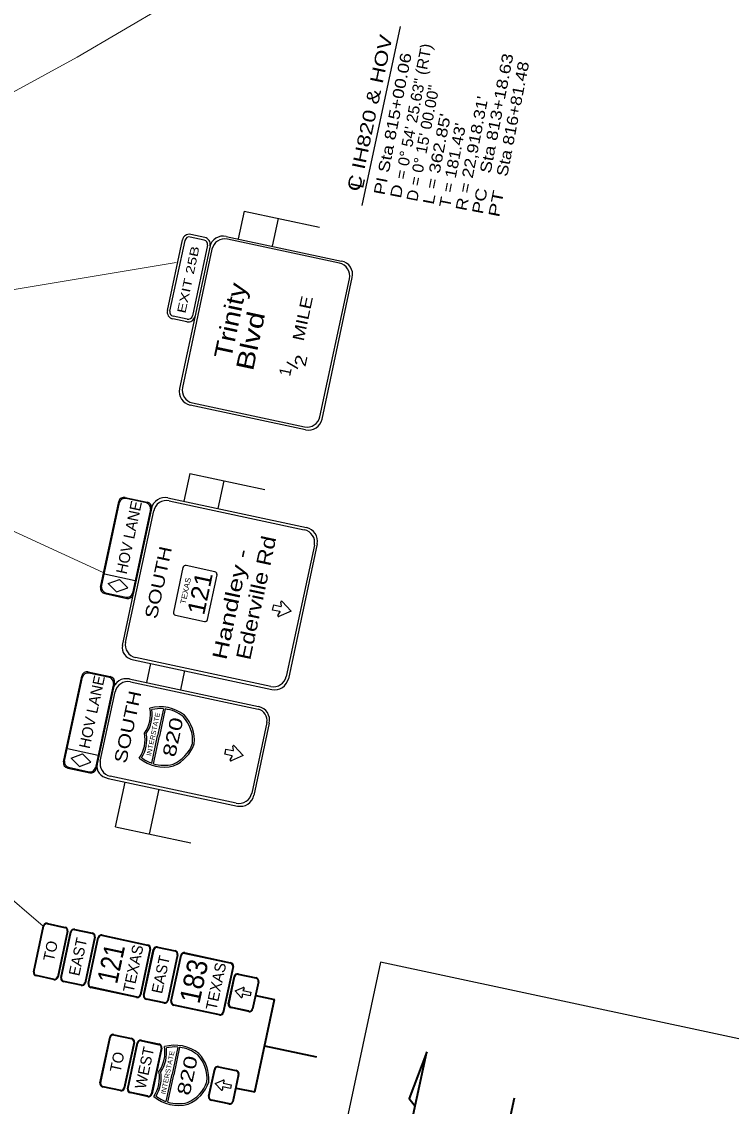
# Model space of a CAD drawing. Extents: x 2363411 to 2369702, y 6977197 to 6988655.
# Drawn here: x 2365781 to 2366546, y 6980518 to 6981687 of the extents above; entities that cross this region are included whole.
import ezdxf
from ezdxf.enums import TextEntityAlignment as Align

# ---------------------------------------------------------------- set-up
doc = ezdxf.new("R2010")
doc.units = 0
doc.header["$LTSCALE"] = 5.6
for name, color, linetype, lineweight in [('1', 7, 'Continuous', 25), ('48', 7, 'Continuous', 25), ('55', 7, 'Continuous', 35), ('61', 7, 'Continuous', 25)]:
    doc.layers.add(name, color=color, linetype=linetype, lineweight=lineweight)
doc.layers.add('28', color=7, linetype='Continuous')
doc.layers.add('33', color=7, linetype='Continuous')

msp = doc.modelspace()

# ---------------------------------------------------------------- linework, layer by layer
at = {"layer": '1'}
for p, q in [((2366020.874, 6981482.752), (2366014.484, 6981452.844)), ((2366020.874, 6981482.752), (2366101.929, 6981465.434)), ((2366057.546, 6981474.917), (2366051.157, 6981445.01)), ((2365937.928, 6981375.61), (2365954.223, 6981451.889)), ((2365940.673, 6981375.022), (2365956.98, 6981451.303)), ((2365977.633, 6981451.687), (2365962.542, 6981454.91)), ((2365978.222, 6981454.434), (2365963.131, 6981457.664)), ((2366001.485, 6981455.621), (2366125.875, 6981429.054)), ((2366123.454, 6981426.696), (2366002.732, 6981452.481)), ((2365983.992, 6981445.538), (2365951.081, 6981291.529)), ((2365986.041, 6981441.669), (2365954.233, 6981292.777)), ((2365981.232, 6981446.123), (2365964.937, 6981369.836)), ((2366102.449, 6981261.107), (2366134.266, 6981410)), ((2366104.809, 6981258.685), (2366137.408, 6981411.245)), ((2365959.371, 6981366.23), (2365944.283, 6981369.458)), ((2365958.785, 6981363.482), (2365943.692, 6981366.702)), ((2365965.044, 6981276.087), (2366085.763, 6981250.295)), ((2366087.009, 6981247.152), (2365962.62, 6981273.726)), ((2365962.059, 6981200.025), (2365955.669, 6981170.118)), ((2365962.059, 6981200.026), (2366043.114, 6981182.708)), ((2365998.731, 6981192.19), (2365992.342, 6981162.284)), ((2365938.629, 6981173.659), (2366088.081, 6981141.727)), ((2365939.875, 6981170.516), (2366085.66, 6981139.368)), ((2365889.641, 6981014.408), (2365920.825, 6981162.123)), ((2365892.852, 6981017.827), (2365923.184, 6981159.702)), ((2366099.617, 6981123.924), (2366068.501, 6980978.416)), ((2366096.474, 6981122.678), (2366066.211, 6980981.14)), ((2365989.318, 6981094.073), (2365958.086, 6981100.752)), ((2365954.749, 6981098.595), (2365944.455, 6981050.436)), ((2365981.189, 6981042.587), (2365991.483, 6981090.738)), ((2366052.66, 6981058.26), (2366060.262, 6981056.638)), ((2366060.882, 6981057.216), (2366060.308, 6981061.315)), ((2365946.622, 6981047.1), (2365977.854, 6981040.421)), ((2366057.212, 6981046.809), (2366059.404, 6981050.343)), ((2365901.323, 6980999.123), (2366050.766, 6980967.183)), ((2366049.52, 6980970.325), (2365903.73, 6981001.475)), ((2365919.718, 6980995.191), (2365915.286, 6980974.449)), ((2365956.392, 6980987.352), (2365951.96, 6980966.611)), ((2365896.913, 6980978.375), (2366036.356, 6980948.576)), ((2365898.167, 6980975.241), (2366035.77, 6980945.833)), ((2365862.329, 6980886.498), (2365879.794, 6980969.113)), ((2365865.54, 6980889.917), (2365881.463, 6980964.428)), ((2365933.712, 6980946.302), (2365927.444, 6980916.965)), ((2365935.604, 6980946.092), (2365929.295, 6980916.571)), ((2366045.2, 6980931.621), (2366028.906, 6980855.365)), ((2366047.89, 6980930.773), (2366031.196, 6980852.641)), ((2365921.179, 6980887.628), (2365927.444, 6980916.965)), ((2365922.988, 6980887.028), (2365929.295, 6980916.571)), ((2366001.085, 6980902.773), (2366008.687, 6980901.151)), ((2366009.307, 6980901.729), (2366008.733, 6980905.828)), ((2366005.637, 6980891.322), (2366007.829, 6980894.856)), ((2365874.011, 6980871.213), (2366013.471, 6980841.403)), ((2366012.224, 6980844.544), (2365876.418, 6980873.565)), ((2365882.061, 6980818.959), (2365892.386, 6980867.285)), ((2365918.732, 6980811.123), (2365929.06, 6980859.446)), ((2365882.061, 6980818.959), (2365963.115, 6980801.639)), ((2365949.29, 6980581.459), (2365943.024, 6980552.121)), ((2365951.181, 6980581.248), (2365944.872, 6980551.729)), ((2365936.757, 6980522.785), (2365943.024, 6980552.121)), ((2365938.564, 6980522.185), (2365944.872, 6980551.729))]:
    msp.add_line(p, q, dxfattribs=at)
at = {"layer": '1', "lineweight": 13}
for p, q in [((2365325.995, 6981323.206), (2365947.601, 6981427.566)), ((2365421.362, 6981299.52), (2365868.555, 6981093.178)), ((2365520.812, 6980952.701), (2365803.961, 6980712.038))]:
    msp.add_line(p, q, dxfattribs=at)
msp.add_lwpolyline([(2365607.98, 6981522.117), (2365840.659, 6981648.883), (2366127.574, 6981817.426)], dxfattribs=at)
at = {"layer": '1'}
for points in [[(2366059.08, 6981051.1), (2366051.464, 6981052.719), (2366052.058, 6981055.49), (2366052.66, 6981058.26)], [(2366061.633, 6981061.904), (2366071.396, 6981051.364), (2366058.176, 6981045.725)], [(2366007.505, 6980895.613), (2365999.889, 6980897.232), (2366000.483, 6980900.003), (2366001.085, 6980902.773)], [(2366010.058, 6980906.417), (2366019.821, 6980895.877), (2366006.601, 6980890.238)]]:
    msp.add_lwpolyline(points, dxfattribs=at)
for centre, radius, start, end in [((2365961.547, 6981450.334), 7.501, 77.93922, 167.93922), ((2365961.547, 6981450.334), 4.688, 77.93922, 167.93922), ((2365976.657, 6981447.105), 4.688, 347.93922, 77.93922), ((2365976.657, 6981447.105), 7.501, 347.93922, 77.93922), ((2365998.358, 6981440.961), 15.001, 77.93922, 167.93922), ((2365999.799, 6981438.736), 14.063, 77.93922, 167.93922), ((2366122.74, 6981414.385), 15.001, 347.93922, 77.93922), ((2366120.515, 6981412.943), 14.063, 347.93922, 77.93922), ((2365945.247, 6981374.049), 7.501, 167.93922, 257.93922), ((2365945.247, 6981374.049), 4.688, 167.93922, 257.93922), ((2365960.357, 6981370.82), 7.501, 257.93922, 347.93922), ((2365960.357, 6981370.82), 4.688, 257.93922, 347.93922), ((2365965.76, 6981288.398), 15.001, 167.93922, 257.93922), ((2365967.986, 6981289.84), 14.063, 167.93922, 257.93922), ((2366088.701, 6981264.047), 14.063, 257.93922, 347.93922), ((2366090.143, 6981261.822), 15.001, 257.93922, 347.93922), ((2365935.494, 6981158.989), 15.001, 77.94013, 167.94013), ((2365936.936, 6981156.763), 14.063, 77.94013, 167.94013), ((2366082.722, 6981125.616), 14.063, 347.94013, 77.94013), ((2366084.947, 6981127.058), 15.001, 347.94013, 77.94013), ((2365957.501, 6981098), 2.813, 77.93906, 167.93906), ((2365988.728, 6981091.328), 2.813, 347.93906, 77.93906), ((2366060.387, 6981057.133), 0.506, 257.93835, 7.92145), ((2366061.064, 6981061.413), 0.759, 42.67684, 188.05798), ((2365947.212, 6981049.847), 2.813, 167.93906, 257.93906), ((2365978.44, 6981043.175), 2.813, 257.93906, 347.93906), ((2366057.86, 6981046.415), 0.759, 147.81871, 293.19985), ((2366058.991, 6981050.598), 0.506, 327.95524, 77.93835), ((2365906.673, 6981015.225), 14.063, 167.94013, 257.94013), ((2365893.789, 6980963.712), 15.001, 77.94013, 167.94013), ((2365895.23, 6980961.486), 14.063, 77.94013, 167.94013), ((2366052.458, 6980984.078), 14.063, 257.94013, 347.94013), ((2366053.9, 6980981.852), 15.001, 257.94013, 347.94013), ((2365930.397, 6980906.367), 41.954, 51.80243, 105.50481), ((2366033.221, 6980933.907), 15, 347.93924, 77.93716), ((2365883.741, 6980940.564), 35.984, 325.11963, 9.96995), ((2365883.741, 6980940.564), 37.874, 326.31755, 7.31439), ((2365930.397, 6980906.367), 40.064, 85.24888, 103.11363), ((2365930.397, 6980906.367), 40.064, 52.01897, 82.53095), ((2365926.405, 6980911.766), 38.808, 355.77729, 42.42367), ((2365926.405, 6980911.766), 40.698, 355.41114, 42.64704), ((2366033.221, 6980933.907), 12.195, 347.93924, 77.93716), ((2365877.909, 6980913.269), 35.984, 325.90855, 10.75886), ((2365877.909, 6980913.269), 37.874, 328.56411, 9.56095), ((2365928.617, 6980922.117), 38.808, 293.45483, 340.10121), ((2365928.617, 6980922.117), 40.698, 293.23145, 340.46735), ((2366008.812, 6980901.647), 0.506, 257.93835, 7.92145), ((2366009.489, 6980905.927), 0.759, 42.67684, 188.05798), ((2365879.361, 6980887.315), 14.063, 167.94013, 257.94013), ((2365934.466, 6980925.413), 41.954, 230.37369, 284.07606), ((2365934.466, 6980925.413), 40.064, 232.76486, 250.62962), ((2366006.284, 6980890.929), 0.759, 147.81871, 293.19985), ((2366007.415, 6980895.111), 0.506, 327.95524, 77.93835), ((2365934.466, 6980925.413), 40.064, 253.34754, 283.85953), ((2366015.153, 6980858.303), 14.063, 257.94013, 347.94013), ((2366016.595, 6980856.077), 15.001, 257.94013, 347.94013), ((2365899.319, 6980575.722), 35.984, 325.11936, 9.96967), ((2365899.319, 6980575.722), 37.874, 326.31727, 7.31411), ((2365945.975, 6980541.524), 41.954, 51.80216, 105.50453), ((2365945.975, 6980541.524), 40.064, 85.2486, 103.11335), ((2365945.975, 6980541.524), 40.064, 52.01869, 82.53068), ((2365941.983, 6980546.923), 40.698, 355.41087, 42.64677), ((2365941.983, 6980546.923), 38.808, 355.77701, 42.42339), ((2365893.487, 6980548.426), 35.984, 325.90827, 10.75858), ((2365893.487, 6980548.426), 37.874, 328.56383, 9.56067), ((2365944.195, 6980557.274), 38.808, 293.45455, 340.10093), ((2365944.195, 6980557.274), 40.698, 293.23117, 340.46707), ((2365950.044, 6980560.57), 41.954, 230.37341, 284.07578), ((2365950.044, 6980560.57), 40.064, 232.76459, 250.62934), ((2365950.044, 6980560.57), 40.064, 253.34726, 283.85925)]:
    msp.add_arc(centre, radius, start, end, dxfattribs=at)
for centre in [(2365904.485, 6981011.715), (2365877.173, 6980883.805)]:
    msp.add_ellipse(centre, major_axis=(-15.18, 0), ratio=0.848877, start_param=6.07270093, end_param=7.64349725, dxfattribs=at)
at = {"layer": '48'}
for p, q in [((2365865.834, 6981077.419), (2365885.547, 6981169.662)), ((2365892.556, 6981174.204), (2365916.282, 6981169.134)), ((2365915.328, 6981168.208), (2365893.045, 6981172.969)), ((2365867.066, 6981077.911), (2365886.464, 6981168.708)), ((2365919.586, 6981161.629), (2365900.189, 6981070.832)), ((2365920.825, 6981162.123), (2365901.12, 6981069.878)), ((2365869.991, 6981091.6), (2365903.114, 6981084.522)), ((2365874.213, 6981081.201), (2365886.141, 6981085.701)), ((2365883.26, 6981072.218), (2365874.213, 6981081.201)), ((2365883.26, 6981072.218), (2365895.188, 6981076.719)), ((2365895.188, 6981076.719), (2365886.141, 6981085.701)), ((2365870.378, 6981070.406), (2365894.234, 6981065.309)), ((2365871.332, 6981071.335), (2365893.616, 6981066.572)), ((2365852.645, 6980986.009), (2365876.371, 6980980.939)), ((2365875.418, 6980980.013), (2365853.134, 6980984.774)), ((2365825.923, 6980889.224), (2365845.636, 6980981.467)), ((2365827.155, 6980889.716), (2365846.553, 6980980.513)), ((2365879.675, 6980973.434), (2365860.278, 6980882.637)), ((2365880.914, 6980973.928), (2365861.209, 6980881.683)), ((2365830.08, 6980903.405), (2365863.203, 6980896.327)), ((2365834.302, 6980893.006), (2365846.23, 6980897.506)), ((2365843.349, 6980884.023), (2365834.302, 6980893.006)), ((2365855.277, 6980888.524), (2365846.23, 6980897.506)), ((2365830.467, 6980882.211), (2365854.323, 6980877.114)), ((2365831.422, 6980883.14), (2365853.705, 6980878.377)), ((2365843.349, 6980884.023), (2365855.277, 6980888.524)), ((2365808.358, 6980714.239), (2365827.441, 6980710.162)), ((2365808.518, 6980714.991), (2365827.601, 6980710.913)), ((2365793.42, 6980662.707), (2365803.961, 6980712.038)), ((2365794.171, 6980662.547), (2365804.712, 6980711.877)), ((2365829.803, 6980706.516), (2365819.263, 6980657.185)), ((2365830.554, 6980706.356), (2365820.014, 6980657.025)), ((2365822.947, 6980656.398), (2365833.488, 6980705.729)), ((2365823.698, 6980656.238), (2365834.239, 6980705.568)), ((2365837.885, 6980707.93), (2365856.968, 6980703.853)), ((2365838.045, 6980708.682), (2365857.128, 6980704.604)), ((2365867.572, 6980702.373), (2365916.903, 6980691.832)), ((2365859.33, 6980700.207), (2365848.79, 6980650.876)), ((2365860.081, 6980700.047), (2365849.541, 6980650.716)), ((2365852.474, 6980650.089), (2365863.015, 6980699.42)), ((2365853.225, 6980649.929), (2365863.766, 6980699.259)), ((2365867.412, 6980701.622), (2365916.743, 6980691.081)), ((2365919.105, 6980687.435), (2365908.564, 6980638.104)), ((2365919.856, 6980687.275), (2365909.316, 6980637.944)), ((2365912.249, 6980637.317), (2365922.79, 6980686.648)), ((2365913, 6980637.157), (2365923.541, 6980686.487)), ((2365927.187, 6980688.849), (2365946.27, 6980684.772)), ((2365927.347, 6980689.601), (2365946.43, 6980685.523)), ((2365948.632, 6980681.126), (2365938.091, 6980631.795)), ((2365949.383, 6980680.966), (2365938.843, 6980631.635)), ((2365941.776, 6980631.008), (2365952.317, 6980680.339)), ((2365942.527, 6980630.848), (2365953.068, 6980680.178)), ((2365956.714, 6980682.541), (2366006.045, 6980672)), ((2365956.874, 6980683.292), (2366006.205, 6980672.751)), ((2366008.407, 6980668.354), (2365997.866, 6980619.023)), ((2366009.158, 6980668.194), (2365998.617, 6980618.863)), ((2365815.456, 6980654.072), (2365796.373, 6980658.149)), ((2365815.616, 6980654.823), (2365796.534, 6980658.9)), ((2366003.699, 6980628.288), (2366009.944, 6980657.514)), ((2366004.45, 6980628.128), (2366010.695, 6980657.354)), ((2366014.341, 6980659.716), (2366033.424, 6980655.639)), ((2366014.501, 6980660.467), (2366033.584, 6980656.39)), ((2365844.983, 6980647.763), (2365825.9, 6980651.84)), ((2365845.143, 6980648.514), (2365826.061, 6980652.591)), ((2365904.758, 6980634.991), (2365855.427, 6980645.531)), ((2365904.918, 6980635.742), (2365855.588, 6980646.282)), ((2366035.786, 6980651.993), (2366029.541, 6980622.767)), ((2366036.537, 6980651.832), (2366030.292, 6980622.606)), ((2365934.285, 6980628.682), (2365915.202, 6980632.759)), ((2365934.445, 6980629.433), (2365915.363, 6980633.51)), ((2365994.06, 6980615.91), (2365944.729, 6980626.45)), ((2365994.22, 6980616.661), (2365944.89, 6980627.201)), ((2366025.735, 6980619.653), (2366006.652, 6980623.731)), ((2366025.895, 6980620.404), (2366006.812, 6980624.482)), ((2365865.258, 6980542.937), (2365875.798, 6980592.268)), ((2365866.009, 6980542.777), (2365876.549, 6980592.107)), ((2365880.195, 6980594.469), (2365899.278, 6980590.392)), ((2365880.356, 6980595.221), (2365899.439, 6980591.143)), ((2365901.64, 6980586.746), (2365891.1, 6980537.415)), ((2365902.391, 6980586.586), (2365891.851, 6980537.255)), ((2365894.785, 6980536.628), (2365905.325, 6980585.959)), ((2365895.536, 6980536.468), (2365906.076, 6980585.798)), ((2365909.722, 6980588.16), (2365928.805, 6980584.083)), ((2365909.883, 6980588.912), (2365928.966, 6980584.834)), ((2365931.167, 6980580.437), (2365920.627, 6980531.106)), ((2365931.918, 6980580.277), (2365921.378, 6980530.946)), ((2365982.362, 6980528.427), (2365988.606, 6980557.653)), ((2365983.113, 6980528.266), (2365989.358, 6980557.492)), ((2365993.004, 6980559.855), (2366012.086, 6980555.777)), ((2365993.164, 6980560.606), (2366012.247, 6980556.528)), ((2366014.449, 6980552.131), (2366008.204, 6980522.905)), ((2366015.2, 6980551.971), (2366008.955, 6980522.745)), ((2365887.293, 6980534.302), (2365868.211, 6980538.379)), ((2365887.454, 6980535.053), (2365868.371, 6980539.13)), ((2365916.82, 6980527.993), (2365897.738, 6980532.07)), ((2365916.981, 6980528.744), (2365897.898, 6980532.821)), ((2366004.397, 6980519.792), (2365985.315, 6980523.869)), ((2366004.558, 6980520.543), (2365985.475, 6980524.62))]:
    msp.add_line(p, q, dxfattribs=at)
at = {"layer": '48', "lineweight": 40}
for p, q in [((2366032.186, 6980533.061), (2366053.523, 6980632.923)), ((2366033.415, 6980637.219), (2366053.523, 6980632.923)), ((2366042.854, 6980582.992), (2366098.689, 6980571.062)), ((2366012.077, 6980537.358), (2366032.186, 6980533.061))]:
    msp.add_line(p, q, dxfattribs=at)
at = {"layer": '48'}
for points in [[(2366017.428, 6980635.113), (2366010.943, 6980642.094), (2366019.637, 6980645.795)], [(2366020.627, 6980644.749), (2366019.484, 6980642.441), (2366028.139, 6980640.591), (2366027.295, 6980636.636), (2366018.639, 6980638.486), (2366018.772, 6980635.661)], [(2365996.09, 6980535.252), (2365989.606, 6980542.233), (2365998.299, 6980545.934)], [(2365999.29, 6980544.889), (2365998.147, 6980542.58), (2366006.801, 6980540.731), (2366005.957, 6980536.775), (2365997.302, 6980538.625), (2365997.434, 6980535.8)]]:
    msp.add_lwpolyline(points, dxfattribs=at)
for centre, radius, start, end in [((2365891.324, 6981168.427), 5.909, 77.93633, 167.93633), ((2365891.892, 6981167.55), 5.54, 77.93633, 167.93633), ((2365914.17, 6981162.786), 5.54, 347.93633, 77.93633), ((2365915.047, 6981163.354), 5.909, 347.93633, 77.93633), ((2365871.613, 6981076.184), 5.909, 167.93575, 257.93575), ((2365872.489, 6981076.752), 5.54, 167.93575, 257.93575), ((2365894.774, 6981071.99), 5.54, 257.93575, 347.93575), ((2365895.342, 6981071.113), 5.909, 257.93575, 347.93575), ((2365851.413, 6980980.232), 5.909, 77.93633, 167.93633), ((2365851.981, 6980979.355), 5.54, 77.93633, 167.93633), ((2365874.259, 6980974.591), 5.54, 347.93633, 77.93633), ((2365875.136, 6980975.159), 5.909, 347.93633, 77.93633), ((2365831.702, 6980887.989), 5.909, 167.93575, 257.93575), ((2365832.578, 6980888.557), 5.54, 167.93575, 257.93575), ((2365854.863, 6980883.794), 5.54, 257.93575, 347.93575), ((2365855.431, 6980882.918), 5.909, 257.93575, 347.93575), ((2365807.716, 6980711.235), 3.84, 77.93906, 167.93906), ((2365807.716, 6980711.235), 3.072, 77.93906, 167.93906), ((2365826.799, 6980707.158), 3.072, 347.93906, 77.93906), ((2365826.799, 6980707.158), 3.84, 347.93906, 77.93906), ((2365837.243, 6980704.926), 3.84, 77.93906, 167.93906), ((2365837.243, 6980704.926), 3.072, 77.93906, 167.93906), ((2365856.326, 6980700.849), 3.072, 347.93906, 77.93906), ((2365856.326, 6980700.849), 3.84, 347.93906, 77.93906), ((2365866.77, 6980698.617), 3.84, 77.93906, 167.93906), ((2365866.77, 6980698.617), 3.072, 77.93906, 167.93906), ((2365916.101, 6980688.077), 3.072, 347.93906, 77.93906), ((2365916.101, 6980688.077), 3.84, 347.93906, 77.93906), ((2365926.545, 6980685.845), 3.84, 77.93906, 167.93906), ((2365926.545, 6980685.845), 3.072, 77.93906, 167.93906), ((2365945.628, 6980681.768), 3.072, 347.93906, 77.93906), ((2365945.628, 6980681.768), 3.84, 347.93906, 77.93906), ((2365956.072, 6980679.536), 3.84, 77.93906, 167.93906), ((2365956.072, 6980679.536), 3.072, 77.93906, 167.93906), ((2366005.403, 6980668.996), 3.072, 347.93906, 77.93906), ((2366005.403, 6980668.996), 3.84, 347.93906, 77.93906), ((2365797.176, 6980661.905), 3.84, 167.93906, 257.93906), ((2365797.176, 6980661.905), 3.072, 167.93906, 257.93906), ((2365816.258, 6980657.827), 3.84, 257.93906, 347.93906), ((2365816.258, 6980657.827), 3.072, 257.93906, 347.93906), ((2365826.703, 6980655.596), 3.84, 167.93906, 257.93906), ((2365826.703, 6980655.596), 3.072, 167.93906, 257.93906), ((2366013.699, 6980656.712), 3.84, 77.93906, 167.93906), ((2366013.699, 6980656.712), 3.072, 77.93906, 167.93906), ((2366032.782, 6980652.635), 3.072, 347.93906, 77.93906), ((2366032.782, 6980652.635), 3.84, 347.93906, 77.93906), ((2365845.785, 6980651.518), 3.84, 257.93906, 347.93906), ((2365845.785, 6980651.518), 3.072, 257.93906, 347.93906), ((2365856.23, 6980649.287), 3.84, 167.93906, 257.93906), ((2365856.23, 6980649.287), 3.072, 167.93906, 257.93906), ((2366019.938, 6980645.089), 0.767, 333.43756, 113.07618), ((2365905.56, 6980638.746), 3.84, 257.93906, 347.93906), ((2365905.56, 6980638.746), 3.072, 257.93906, 347.93906), ((2365916.005, 6980636.515), 3.84, 167.93906, 257.93906), ((2365916.005, 6980636.515), 3.072, 167.93906, 257.93906), ((2365935.087, 6980632.437), 3.072, 257.93906, 347.93906), ((2366017.995, 6980635.628), 0.767, 222.92454, 2.65311), ((2365935.087, 6980632.437), 3.84, 257.93906, 347.93906), ((2365945.532, 6980630.206), 3.84, 167.93906, 257.93906), ((2365945.532, 6980630.206), 3.072, 167.93906, 257.93906), ((2366007.454, 6980627.486), 3.84, 167.93906, 257.93906), ((2366007.454, 6980627.486), 3.072, 167.93906, 257.93906), ((2366026.537, 6980623.409), 3.84, 257.93906, 347.93906), ((2366026.537, 6980623.409), 3.072, 257.93906, 347.93906), ((2365994.862, 6980619.665), 3.84, 257.93906, 347.93906), ((2365994.862, 6980619.665), 3.072, 257.93906, 347.93906), ((2365879.553, 6980591.465), 3.84, 77.93906, 167.93906), ((2365879.553, 6980591.465), 3.072, 77.93906, 167.93906), ((2365898.636, 6980587.388), 3.072, 347.93906, 77.93906), ((2365898.636, 6980587.388), 3.84, 347.93906, 77.93906), ((2365909.08, 6980585.156), 3.84, 77.93906, 167.93906), ((2365909.08, 6980585.156), 3.072, 77.93906, 167.93906), ((2365928.163, 6980581.079), 3.072, 347.93906, 77.93906), ((2365928.163, 6980581.079), 3.84, 347.93906, 77.93906), ((2365992.362, 6980556.85), 3.84, 77.93906, 167.93906), ((2365992.362, 6980556.85), 3.072, 77.93906, 167.93906), ((2366011.444, 6980552.773), 3.072, 347.93906, 77.93906), ((2366011.444, 6980552.773), 3.84, 347.93906, 77.93906), ((2365869.013, 6980542.135), 3.84, 167.93906, 257.93906), ((2365869.013, 6980542.135), 3.072, 167.93906, 257.93906), ((2365998.601, 6980545.228), 0.767, 333.43756, 113.07618), ((2365888.096, 6980538.057), 3.84, 257.93906, 347.93906), ((2365888.096, 6980538.057), 3.072, 257.93906, 347.93906), ((2365898.54, 6980535.826), 3.84, 167.93906, 257.93906), ((2365898.54, 6980535.826), 3.072, 167.93906, 257.93906), ((2365917.623, 6980531.748), 3.84, 257.93906, 347.93906), ((2365917.623, 6980531.748), 3.072, 257.93906, 347.93906), ((2365986.117, 6980527.625), 3.84, 167.93906, 257.93906), ((2365986.117, 6980527.625), 3.072, 167.93906, 257.93906), ((2365996.658, 6980535.767), 0.767, 222.92454, 2.65311), ((2366005.2, 6980523.547), 3.84, 257.93906, 347.93906), ((2366005.2, 6980523.547), 3.072, 257.93906, 347.93906)]:
    msp.add_arc(centre, radius, start, end, dxfattribs=at)
at = {"layer": '55'}
for p, q in [((2366178.944, 6980394.843), (2366217.725, 6980576.345)), ((2366311.984, 6980526.529), (2366218.153, 6980084.816))]:
    msp.add_line(p, q, dxfattribs=at)
msp.add_lwpolyline([(2366217.725, 6980576.345), (2366198.873, 6980525.975), (2366205.188, 6980517.668)], dxfattribs=at)
at = {"layer": '61'}
msp.add_line((2366148.088, 6981488.944), (2366189.323, 6981681.932), dxfattribs=at)
msp.add_lwpolyline([(2366482.339, 6979717.696), (2366663.815, 6980567.032), (2366167.737, 6980673.028), (2365986.261, 6979823.692)], close=True, dxfattribs=at)

# ---------------------------------------------------------------- texts
at = {"layer": '1'}
for s, height, rotation, width, p in [('EXIT 25B', 9.188, 77.939, 1.4, (2365964.978, 6981408.012)), ('Trinity', 18.91, 77.939, 1.2, (2366015.236, 6981362.735)), ('MILE', 12.54, 77.939, 1.25, (2366090.018, 6981365.896)), ('Blvd', 18.9, 77.939, 1.3, (2366036.908, 6981340.976)), ('2', 12.54, 77.939, 1.3, (2366088.012, 6981320.358)), ('1', 12.54, 77.939, 0.95, (2366071.232, 6981308.508)), ('/', 12.54, 77.939, 1.3, (2366079.19, 6981315.239)), ('Ederville Rd', 15.68, 77.94, 1.2, (2366041.347, 6981064.322)), ('SOUTH', 13.5, 77.94, 1.25, (2365934.75, 6981081.069)), ('Handley -', 15.68, 77.94, 1.35, (2366014.113, 6981057.433)), ('SOUTH', 13.5, 77.94, 1.25, (2365901.771, 6980925.32))]:
    msp.add_text(s, height=height, rotation=rotation, dxfattribs=dict(at, width=width)).set_placement(p, align=Align.CENTER)
for s, height, width, p in [('121', 18.75, 1.1, (2365977.479, 6981046.312)), ('TEXAS', 6, 1.1, (2365957.584, 6981058.714)), ('INTERSTATE', 5.198, 1.1, (2365920.299, 6980895.097)), ('820', 14.18, 1.35, (2365946.366, 6980893.348)), ('INTERSTATE', 5.198, 1.1, (2365935.876, 6980530.255)), ('820', 14.18, 1.35, (2365961.945, 6980528.505))]:
    msp.add_text(s, height=height, rotation=77.939, dxfattribs=dict(at, width=width)).set_placement(p)
at = {"layer": '28', "width": 1.3}
msp.add_text('C IH820 & HOV', height=14, rotation=78.048, dxfattribs=at).set_placement((2366163.165, 6981587.154), align=Align.CENTER)
at = {"layer": '33'}
for s, width, p in [('= 0° 54\' 25.63" (RT)', 1.05, (2366195.319, 6981516.378)), ('PI Sta 815+00.06', 1.25, (2366172.103, 6981499.478)), ('Sta 813+18.63', 1.25, (2366286.521, 6981522.886)), ('Sta 816+81.48', 1.2, (2366304.46, 6981519.424)), ('D = 0° 15\' 00.00"', 1.05, (2366207.43, 6981492.661)), ("R = 22,918.31'", 1.2, (2366260.422, 6981482.434)), ("L = 362.85'", 1.25, (2366225.094, 6981489.252)), ("T = 181.43'", 1.15, (2366242.758, 6981485.843)), ('D', 1.25, (2366189.767, 6981496.069)), ('PC', 1.25, (2366278.087, 6981479.025)), ('PT', 1.4, (2366295.751, 6981475.616))]:
    msp.add_text(s, height=12, rotation=79.077, dxfattribs=dict(at, width=width)).set_placement(p)
at = {"layer": '48'}
for s, rotation, p in [('HOV LANE', 77.935, (2365902.288, 6981129.823)), ('HOV LANE', 77.935, (2365862.378, 6980941.627)), ('TO', 77.859, (2365817.702, 6980683.935)), ('EAST', 77.859, (2365847.228, 6980677.625)), ('TEXAS', 77.859, (2365906.892, 6980664.876)), ('EAST', 77.859, (2365936.53, 6980658.544)), ('TEXAS', 77.859, (2365996.193, 6980645.796)), ('TO', 77.859, (2365889.538, 6980564.165)), ('WEST', 77.859, (2365919.065, 6980557.856))]:
    msp.add_text(s, height=11.82, rotation=rotation, dxfattribs=at).set_placement(p, align=Align.CENTER)
for s, width, p in [('121', 0.85, (2365888.05, 6980669.231)), ('183', 0.95, (2365977.351, 6980650.151))]:
    msp.add_text(s, height=22.16, rotation=77.859, dxfattribs=dict(at, width=width)).set_placement(p, align=Align.CENTER)
at = {"layer": '61', "width": 1.05}
msp.add_text('L', height=14, rotation=77.939, dxfattribs=at).set_placement((2366150.125, 6981511.954), align=Align.CENTER)

doc.saveas('drawing.dxf')
